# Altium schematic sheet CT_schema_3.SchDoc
size 395 x 205 mm
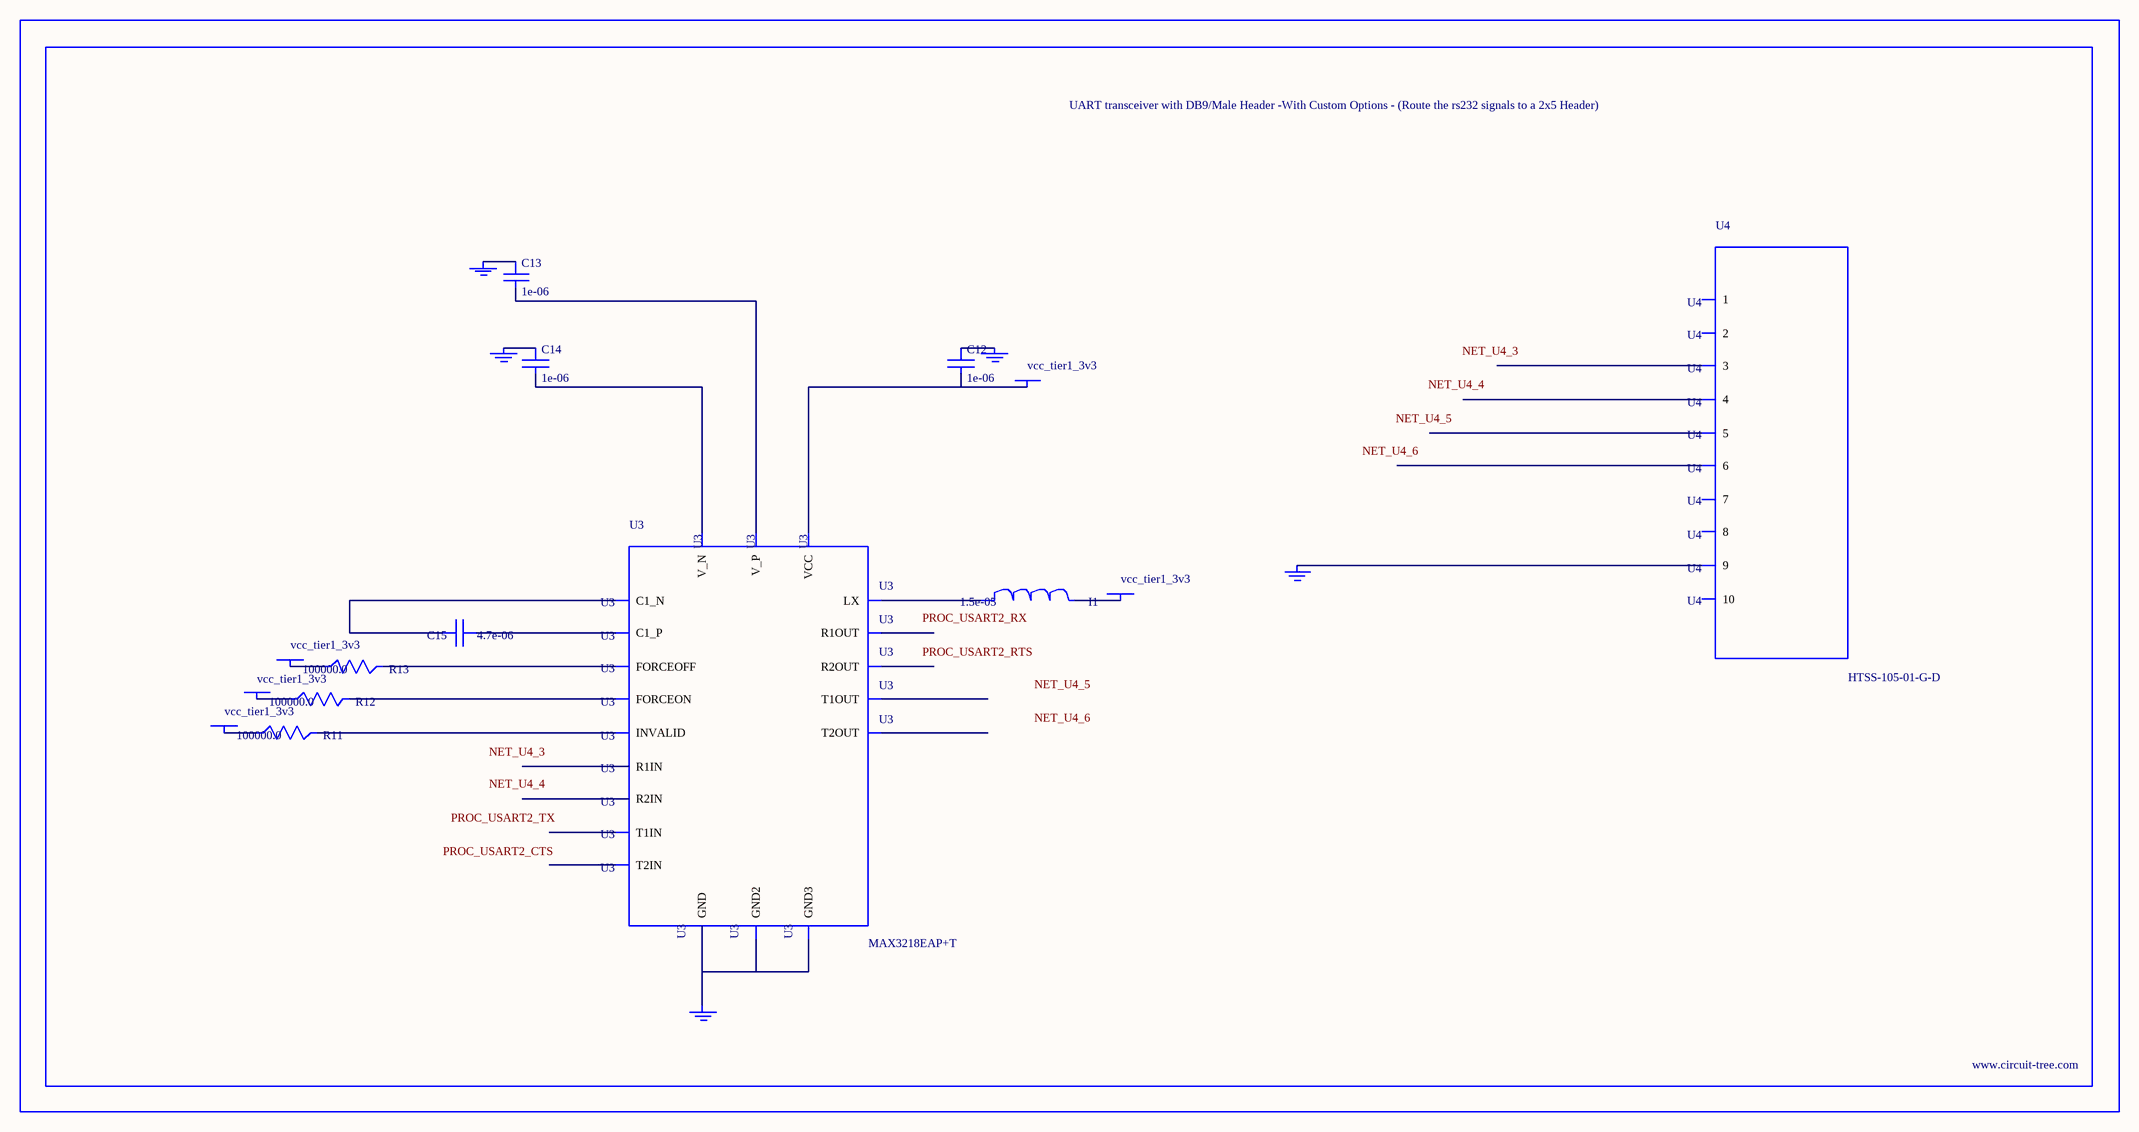
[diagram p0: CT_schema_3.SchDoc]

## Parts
BORDER2  (no value)
C12  1e-06  [C0603]
C13  1e-06  [C0603]
C14  1e-06  [C0603]
C15  4.7e-06  [C0805]
GND_INSTANCE_2_0  (no value)
GND_INSTANCE_2_1  (no value)
GND_INSTANCE_2_2  (no value)
GND_INSTANCE_2_3  (no value)
GND_INSTANCE_2_4  (no value)
I1  1.5e-05  [L1210]
POWER_INSTANCE_2_0  vcc_tier1_3v3
POWER_INSTANCE_2_1  vcc_tier1_3v3
POWER_INSTANCE_2_2  vcc_tier1_3v3
POWER_INSTANCE_2_3  vcc_tier1_3v3
POWER_INSTANCE_2_4  vcc_tier1_3v3
R11  100000.0  [R0603]
R12  100000.0  [R0603]
R13  100000.0  [R0603]
U3  MAX3218EAP+T  [SSOP-20]
U4  HTSS-105-01-G-D  [HTSS-105-01-G-D]

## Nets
NetC12_1: C12.1 GND_INSTANCE_2_0.0(GND)
NetC12_2: C12.2 POWER_INSTANCE_2_4.0(PWR) U3.6(VCC)
NetC13_1: C13.1 GND_INSTANCE_2_2.0(GND)
NetC13_2: C13.2 U3.19(V_P)
NetC14_1: C14.1 GND_INSTANCE_2_1.0(GND)
NetC14_2: C14.2 U3.15(V_N)
NetC15_1: C15.1 U3.18(C1_P)
NetC15_2: C15.2 U3.16(C1_N)
NetGND_INSTANCE_2_3_0: GND_INSTANCE_2_3.0(GND) U3.5(GND) U3.17(GND2) U3.20(GND3)
NetGND_INSTANCE_2_4_0: GND_INSTANCE_2_4.0(GND) U4.9
NetI1_1: I1.1 U3.1(LX)
NetI1_2: I1.2 POWER_INSTANCE_2_0.0(PWR)
NetPOWER_INSTANCE_2_1_0: POWER_INSTANCE_2_1.0(PWR) R11.1
NetPOWER_INSTANCE_2_2_0: POWER_INSTANCE_2_2.0(PWR) R12.1
NetPOWER_INSTANCE_2_3_0: POWER_INSTANCE_2_3.0(PWR) R13.1
NetR11_2: R11.2 U3.2(INVALID)
NetR12_2: R12.2 U3.3(FORCEON)
NetR13_2: R13.2 U3.4(FORCEOFF)

Not connected (* = marked no-connect by the designer): U3 7(T1IN) 8(T2IN) 9(R1OUT) 10(R2OUT) 11(R2IN) 12(R1IN) 13(T2OUT) 14(T1OUT); U4 1 2 3 4 5 6 7 8 10

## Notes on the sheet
- Labels drawn without touching a wire or pin: NET_U4_3, NET_U4_4, NET_U4_5, NET_U4_6, PROC_USART2_CTS, PROC_USART2_RTS, PROC_USART2_RX, PROC_USART2_TX

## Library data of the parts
BORDER2 = BORDER_PAGE2
C12-C14 = C0603C105K3RACTU
C15 = C0805C475K4RACTU
GND_INSTANCE_2_0-GND_INSTANCE_2_4 = GND
I1 = L1210R150MDWIT
POWER_INSTANCE_2_0-POWER_INSTANCE_2_4 = PWR
R11-R13 = RC0603JR-07100KL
